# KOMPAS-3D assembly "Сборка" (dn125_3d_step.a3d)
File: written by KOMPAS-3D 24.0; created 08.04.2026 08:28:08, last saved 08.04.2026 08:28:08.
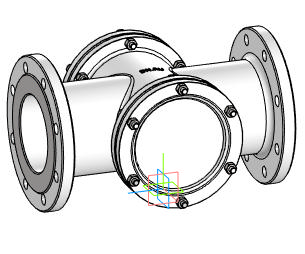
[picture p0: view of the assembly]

Document properties: Автор: Main; Полное имя файла: D:\DN.ru Аутсерс\Стекло смотровое DN.ru\Исходники\Стекло смотровое DN.ru SG2-34G-F тип В ГОСТ 21836-2021 Ду125 Ру16, углеродистая сталь, фланцевое\dn125_3d_step.a3d

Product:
- Component [detail]: Деталь  | qty 1  | Автор: Main; source file: ДетальДеталь.m3d
- Component [detail]: Стекло  | qty 2  | Автор: Main; source file: СтеклоСтекло.m3d
- Component [detail]: ANSI B18.2.4.2M - M10x1,5 - 16  | designation ANSI B18.2.4.2M - M10x1,5  | qty 1  | Автор: Main; source file: ANSI B18.2.4.2M - M10x1,5ANSI B18.2.4.2M - M10x1,5 - 16.m3d
- Component [detail]: ANSI B18.2.4.2M - M10x1,5 - 16  | designation ANSI B18.2.4.2M - M10x1,5  | qty 23  | Комментарий: Типы метрических   шестигранных гаек   2; Автор: Main; additional columns: Сталь, мягкая; source file: ANSI B18.2.4.2M - M10x1,5ANSI B18.2.4.2M - M10x1,5 - 16.m3d
- Part/product: Сборка

Referenced files in D:\DN.ru Аутсерс\Стекло смотровое DN.ru\Исходники\Стекло смотровое DN.ru SG2-34G-F тип В ГОСТ 21836-2021 Ду125 Ру16, углеродистая сталь, фланцевое\: ДетальДеталь.m3d, СтеклоСтекло.m3d, ANSI B18.2.4.2M - M10x1,5ANSI B18.2.4.2M - M10x1,5 - 16.m3d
